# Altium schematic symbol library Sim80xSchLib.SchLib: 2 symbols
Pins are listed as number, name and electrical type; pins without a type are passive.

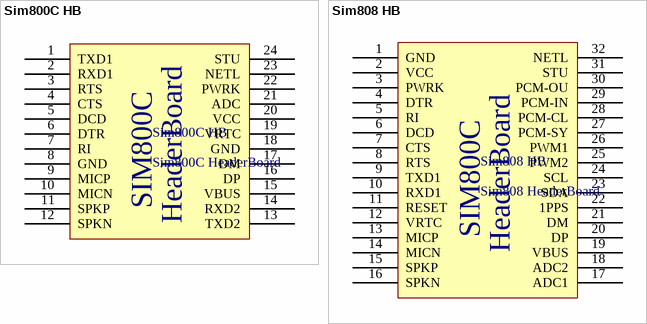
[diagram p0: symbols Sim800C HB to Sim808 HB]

## Sim800C HB
designator Sim800C HB, comment Sim800C HeaderBoard
Shop.RoboticNGO.com
footprint Sim800C Header Board (Sim800C Header Board - Shop.RoboticNGO.com)
pins: 1 TXD1, 2 RXD1, 3 RTS, 4 CTS, 5 DCD, 6 DTR, 7 RI, 8 GND (power), 9 MICP, 10 MICN, 11 SPKP, 12 SPKN, 13 TXD2, 14 RXD2, 15 VBUS, 16 DP, 17 DM, 18 GND (power), 19 VRTC, 20 VCC (power), 21 ADC, 22 PWRK, 23 NETL, 24 STU

## Sim808 HB
designator Sim808 HB, comment Sim808 HeaderBoard
Shop.RoboticNGO.com
footprint Sim808 Header Board (Sim808 Header Board - Shop.RoboticNGO.com)
pins: 1 GND (power), 2 VCC (power), 3 PWRK, 4 DTR, 5 RI, 6 DCD, 7 CTS, 8 RTS, 9 TXD1, 10 RXD1, 11 RESET, 12 VRTC, 13 MICP, 14 MICN, 15 SPKP, 16 SPKN, 17 ADC1, 18 ADC2, 19 VBUS, 20 DP, 21 DM, 22 1PPS, 23 SDA, 24 SCL, 25 PWM2, 26 PWM1, 27 PCM-SY, 28 PCM-CL, 29 PCM-IN, 30 PCM-OU, 31 STU, 32 NETL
